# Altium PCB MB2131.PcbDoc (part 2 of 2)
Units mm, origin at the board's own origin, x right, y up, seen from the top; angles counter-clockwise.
Board outline 22 x 56 mm, 2 copper layers (Top Layer, Bottom Layer), stack 0.87 mm thick; 89 components, 71 nets, 391 pads, 308 vias.
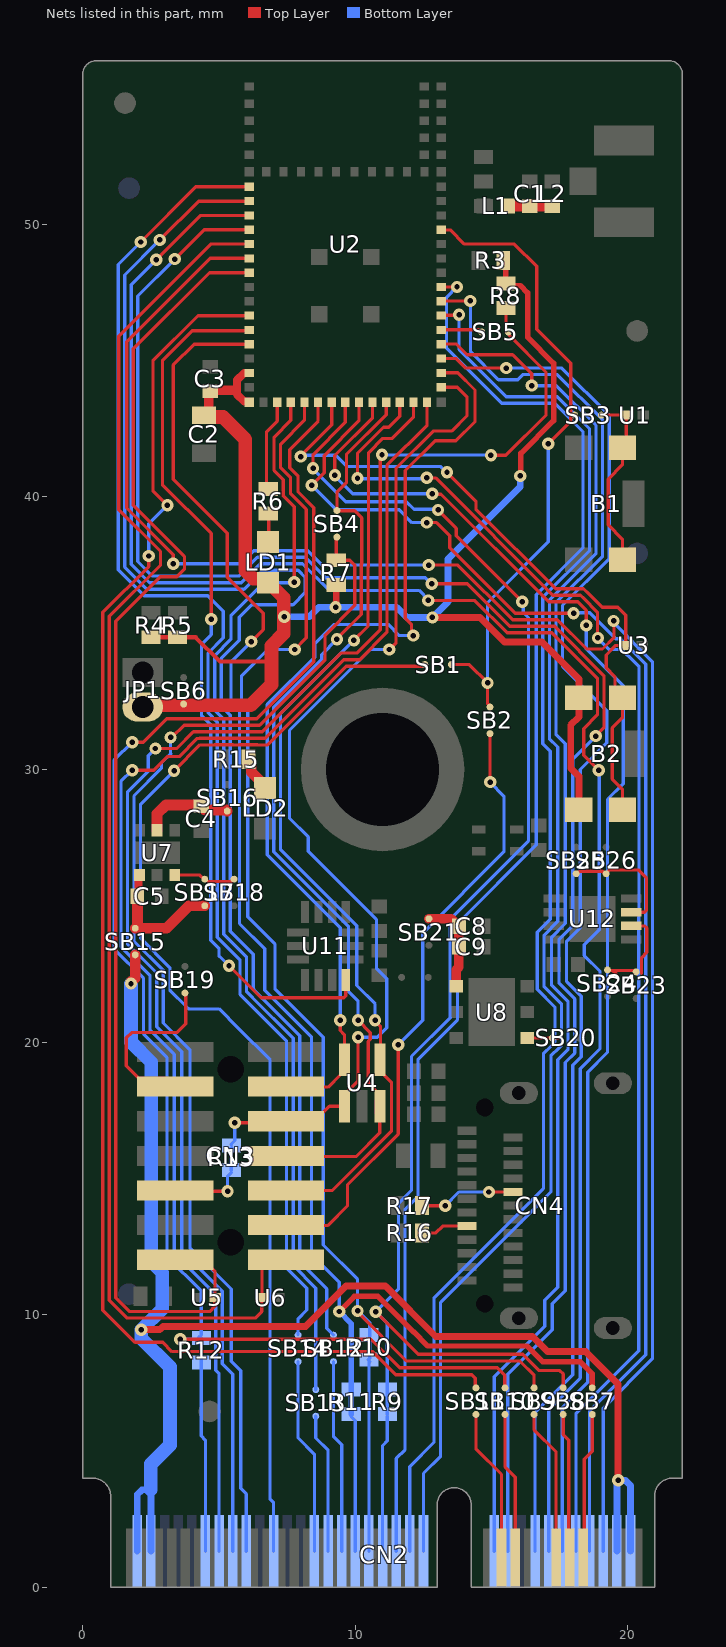
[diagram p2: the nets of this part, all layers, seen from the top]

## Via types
v1: diameter 0.45, hole 0.2, Top Layer to Bottom Layer, tented both sides, 308 vias

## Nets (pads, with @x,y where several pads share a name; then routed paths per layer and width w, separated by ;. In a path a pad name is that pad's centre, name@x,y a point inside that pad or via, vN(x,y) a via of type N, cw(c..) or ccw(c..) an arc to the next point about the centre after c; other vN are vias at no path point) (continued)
JTDI: CN3.10 U2.34 U4.4 | length 35.1
  Top Layer w0.12: CN3.10@7.457,14.555 9.155,14.555 11.325,16.725 11.325,18.525 U4.4@11.025,18.825 ; v1(9.949,34.734) 10.461,35.246 10.461,37.437 10.485,37.461 10.485,41.626 11.005,42.146 11.353,42.146 12.133,42.926 U2.34@12.133,43.475 ; v1(10.725,20.8) 10.725,20.765 10.925,20.565 U4.4@10.925,19.075
  Bottom Layer w0.12: v1(9.949,34.734) 9.943,34.734 7.252,32.043 7.252,27.073 10.05,24.275 10.05,22.075 10.725,21.4 v1(10.725,20.8)
M2_3V3: CN2.2 CN2.4 CN2.72 CN2.74 SB15.1 | length 54.8
  Top Layer w0.25: v1@2.157,9.453 2.828,9.453 2.945,9.57 8.179,9.57 9.659,11.05 11.1,11.05 12.95,9.2 16.5,9.2 17.05,8.65 18.45,8.65 19.641,7.459 v1(19.641,3.922)
  Top Layer w0.4: v1(1.77,22.145) 1.77,22.199 1.925,22.354 SB15.1@1.925,23.2
  Bottom Layer w0.25: 2,3.4 2.174,3.575 2.5,3.575 CN2.72@2.5,1.325 ; CN2.74@2,1.325 2,3.4 ; CN2.4@19.594,1.325 19.594,3.821 19.641,3.868 v1(19.641,3.922) 19.906,3.922 20.094,3.734 CN2.2@20.094,1.325
  Bottom Layer w0.5: v1(1.77,22.145) 1.77,20 2.512,19.258 2.512,11.942 2.914,11.54 2.914,10.21 v1(2.148,9.443) 2.148,9.13 3.2,8.078 3.2,5.22 2.5,4.52 2.5,3.575
NetB1_1: B1.1 B1.3 SB3.2 U1.1 | length 6.6
  Top Layer w0.12: SB3.2@19.025,43 U1.1@19.938,43 19.938,41.813 B1.3@19.925,41.8 ; B1.1@19.8,37.75 19.8,38.45 19.275,38.975 19.275,40.65 19.8,41.175 B1.3@19.8,41.8
NetB2_1: B2.1 B2.3 U2.28 U3.1 | length 25
  Top Layer w0.12: v1(7.994,41.478) 7.994,41.507 9.133,42.645 U2.28@9.133,43.475 ; v1(13.362,40.905) 14.425,39.842 14.425,39.55 17.345,36.63 18.37,36.63 18.575,36.425 19.05,35.95 19.625,35.95 19.921,35.654 19.921,34.571 U3.1@19.9,34.55 19.55,34.55 19.2,34.2 19.2,33.725 19.525,33.4 B2.3@19.525,32.725 ; B2.1@19.775,28.525 19.8,28.55 19.8,29.275 19.425,29.65 19.425,31.525 19.8,31.9 B2.3@19.8,32.625
  Bottom Layer w0.12: v1(7.994,41.478) 8.042,41.525 9.275,41.525 9.684,41.116 13.116,41.116 13.32,40.912 v1@13.355,40.912
NetC1_2: C1.2 L1.2 L2.1 | length 1.6
  Top Layer w0.4: L1.2@15.6,50.675 C1.2@16.4,50.675 L2.1@17.225,50.675
NetC4_2: C4.2 SB16.1 U7.5 | length 3.4
  Top Layer w0.4: U7.5@2.725,27.775 2.725,28.375 3.05,28.7 4.3,28.7 4.488,28.512 5.263,28.512 SB16.1@5.3,28.475
NetC5_2: C5.2 SB15.2 SB17.1 U7.1 | length 5
  Top Layer w0.3: C5.2@2,25.35 2.042,25.392 2.042,26.092 U7.1@2.075,26.125 2.075,26.15 U7.1@2.025,26.2
  Top Layer w0.4: C5.2@2.004,25.346 2.004,24.254 SB15.2@1.925,24.175 3.071,24.175 3.896,25 SB17.1@4.475,25
NetC8_2: C8.2 C9.2 SB21.1 U8.4 | length 3.4
  Top Layer w0.35: SB21.1@12.7,24.525 13.525,24.525 13.695,24.355 13.72,24.355 13.8,24.275 C8.2@13.8,24.25 C9.2@13.8,23.5 ; U8.4@13.7,22.05 13.7,22.65 13.8,22.75 C9.2@13.8,23.475
NetCN2_6: CN2.6 U2.12 | length 68.7
  Top Layer w0.12: v1(3.325,37.55) 3.325,37.882 1.615,39.592 1.615,45.69 4.675,48.75 U2.12@6.108,48.75 ; v1(12.691,37.499) 13.762,37.499 15.769,35.492 17.412,35.492 18.484,34.42 19.068,34.42 19.492,34.844 19.492,35.432 v1(19.474,35.449)
  Bottom Layer w0.12: v1(3.325,37.55) 5.8,37.55 6.275,38.025 8.26,38.025 8.786,37.499 v1(12.691,37.499) ; CN2.6@19.094,1.325 19.094,6.569 20.9,8.375 20.9,33.958 19.474,35.384 v1(19.474,35.449)
NetCN2_8: CN2.8 U2.30 | length 52.4
  Top Layer w0.12: v1(8.4,40.425) 8.855,40.88 8.855,41.513 10.133,42.79 U2.30@10.133,43.475 ; v1(12.616,39.058) 12.981,39.058 13.465,38.574 13.465,38.135 15.868,35.732 v1(18.005,35.732)
  Bottom Layer w0.12: v1(8.4,40.425) 9.3,39.525 11.611,39.525 12.078,39.058 v1(12.616,39.058) ; v1(18.005,35.732) 18.022,35.749 18.602,35.749 19.551,34.8 19.718,34.8 20.65,33.868 20.65,8.525 18.594,6.469 CN2.8@18.594,1.325
NetCN2_9: CN2.9 SB7.1 | length 5.4
  Top Layer w0.12: CN2.9@18.363,1.075 18.4,1.112 18.4,4.7 18.69,4.99 SB7.1@18.69,6.339
NetCN2_10: CN2.10 U2.33 | length 50.7
  Top Layer w0.12: v1(10.08,40.679) 10.08,41.599 11.033,42.552 11.222,42.552 11.633,42.962 U2.33@11.633,43.475 ; v1(12.616,40.701) 12.623,40.694 12.942,40.694 17.246,36.39 18.26,36.39 18.375,36.275 ; 18.375,36.275 18.882,35.767 18.882,34.843 v1(18.9,34.825)
  Bottom Layer w0.12: v1(10.08,40.679) 10.093,40.666 12.582,40.666 v1(12.616,40.701) ; CN2.10@18.094,1.325 18.094,6.369 20.4,8.675 20.4,24.575 20.41,24.585 20.41,33.765 20.225,33.95 ; v1(18.9,34.825) 18.9,34.812 19.319,34.394 19.325,34.4 19.779,34.4 20.227,33.952
NetCN2_11: CN2.11 SB8.1 | length 5.4
  Top Layer w0.12: SB8.1@17.624,6.339 17.624,5.601 17.825,5.4 17.825,1.112 CN2.11@17.863,1.075
NetCN2_12: CN2.12 U2.31 | length 50.6
  Top Layer w0.12: v1(9.252,40.799) 9.246,40.804 9.246,41.518 10.633,42.904 U2.31@10.633,43.475 ; v1(12.823,40.111) 12.835,40.098 13.143,40.098 17.091,36.15 18.16,36.15 18.476,35.834 v1(18.476,35.284)
  Bottom Layer w0.12: v1(9.252,40.799) 9.252,40.766 9.907,40.111 v1(12.823,40.111) ; CN2.12@17.594,1.325 17.594,6.594 18.525,7.525 18.525,18.9 19.25,19.625 19.25,28.9 19.825,29.475 19.825,33.075 18.468,34.432 18.468,35.276 v1(18.476,35.284)
NetCN2_13: CN2.13 SB9.1 | length 5.6
  Top Layer w0.12: SB9.1@16.558,6.339 16.558,5.767 17.363,4.962 CN2.13@17.363,1.075
NetCN2_14: CN2.14 U2.9 | length 68.9
  Top Layer w0.12: v1(2.7,48.7) 4.325,50.325 5.55,50.325 U2.9@6.108,50.325 ; v1(12.675,36.201) 12.679,36.198 14.384,36.198 15.57,35.012 17.213,35.012 18.88,33.345 18.88,32.005 18.375,31.5 18.375,30.525 v1(18.925,29.975)
  Bottom Layer w0.12: 1.78,37.524 2.449,36.855 5.819,36.855 6.509,37.545 8.061,37.545 9.038,36.569 12.336,36.569 12.675,36.23 v1(12.675,36.201) ; 1.85,37.46 1.78,37.531 1.78,47.78 v1(2.7,48.7) ; CN2.14@17.094,1.325 17.094,6.519 18.25,7.675 18.25,19.025 18.975,19.75 18.975,22.6 18.4,23.175 18.4,23.575 18.95,24.125 18.95,29.95 v1(18.925,29.975)
NetCN2_16: CN2.16 U2.39 | length 51.6
  Top Layer w0.12: U2.39@13.158,45.075 13.709,45.075 14.057,44.727 v1(15.536,44.727)
  Bottom Layer w0.12: v1(15.536,44.727) 17.573,44.727 19.31,42.99 19.31,37.727 17.6,36.017 17.6,33.775 19.225,32.15 19.225,30.975 18.25,30 18.25,24.2 17.75,23.7 17.75,22.218 18.285,21.683 18.285,19.46 18.175,19.35 17.975,19.15 17.975,7.8 16.594,6.419 CN2.16@16.594,1.325
NetCN2_19: CN2.19 SB10.1 | length 5.4
  Top Layer w0.12: SB10.1@15.491,6.339 15.491,4.409 15.863,4.037 CN2.19@15.863,1.075
NetCN2_20: CN2.20 U2.10 | length 68.3
  Top Layer w0.12: v1(3.375,48.725) 4.452,49.802 U2.10@6.108,49.802 ; v1(12.804,36.813) 14.108,36.813 15.669,35.252 17.313,35.252 19.12,33.444 19.12,31.525 v1(18.82,31.225)
  Bottom Layer w0.12: v1(3.375,48.725) 2.02,47.37 2.02,37.63 2.555,37.095 5.72,37.095 6.41,37.785 8.161,37.785 8.916,37.03 12.569,37.03 12.786,36.813 v1(12.804,36.813) ; CN2.20@15.594,1.325 15.594,7.819 17.225,9.45 17.225,10.4 17.7,10.875 17.7,19.25 18.045,19.595 18.045,21.584 17.475,22.154 17.475,23.775 17.975,24.275 17.975,30.38 v1(18.82,31.225)
NetCN2_21: CN2.21 SB11.1 | length 5.7
  Top Layer w0.12: SB11.1@14.425,6.339 14.425,5.075 15.363,4.137 CN2.21@15.363,1.075
NetCN2_22: CN2.22 U2.43 | length 52.9
  Top Layer w0.12: U2.43@13.158,47.175 13.165,47.183 14.208,47.183 v1(14.216,47.19)
  Bottom Layer w0.12: v1(14.216,47.19) 14.229,47.177 14.229,45.321 15.25,44.3 15.954,44.3 16.141,44.487 17.413,44.487 19.07,42.83 19.07,37.827 17.36,36.117 17.36,31.29 17.7,30.95 17.7,24.35 17.2,23.85 17.2,22.089 17.805,21.484 17.805,19.73 17.425,19.35 17.425,11 16.95,10.525 16.95,9.575 15.094,7.719 CN2.22@15.094,1.325
NetCN2_32: CN2.32 U2.40 | length 51.9
  Top Layer w0.12: U2.40@13.158,45.6 13.167,45.609 13.704,45.609 14.096,45.218 15.768,45.218 16.472,44.513 v1(16.472,44.082)
  Bottom Layer w0.12: CN2.32@12.5,1.325 12.5,4.175 13.125,4.8 13.125,10.45 16.375,13.7 17.175,14.5 17.175,19.5 17.475,19.8 17.565,19.89 17.565,21.385 16.925,22.025 16.925,23.925 17.425,24.425 17.425,30.825 17.12,31.13 17.12,36.216 18.83,37.926 18.83,42.62 17.368,44.082 v1(16.472,44.082)
NetCN2_34: CN2.34 U2.42 | length 52.6
  Top Layer w0.12: U2.42@13.158,46.65 13.173,46.666 13.791,46.666 v1(13.807,46.682)
  Bottom Layer w0.12: CN2.34@12,1.325 12,4.425 12.885,5.31 12.885,10.61 16.9,14.625 16.9,19.575 17.2,19.875 17.325,20 17.325,21.286 16.675,21.936 16.675,24.025 17.15,24.5 17.15,30.675 16.88,30.945 16.88,36.316 18.59,38.026 18.59,42.498 17.411,43.677 16.305,43.677 15.533,43.677 13.807,45.404 v1(13.807,46.682)
NetCN2_36: CN2.36 U2.44 | length 53.2
  Top Layer w0.12: U2.44@13.158,47.7 13.158,47.701 v1(13.729,47.702) v1(13.729,47.702)
  Bottom Layer w0.12: CN2.36@11.5,1.325 11.5,4.725 11.825,5.05 11.825,13.875 12.3,14.35 12.3,19.375 13.75,20.825 13.75,24.35 16.64,27.24 16.64,36.415 18.35,38.125 18.35,42.398 17.317,43.431 15.37,43.431 13.347,45.454 13.347,47.32 v1(13.729,47.702)
NetCN2_44: CN2.44 SB12.2 | length 7.1
  Bottom Layer w0.12: SB12.2@9.2,8.275 9.2,5.525 9.5,5.225 CN2.44@9.5,1.325
NetCN2_46: CN2.46 SB13.2 | length 5.1
  Bottom Layer w0.12: SB13.2@8.55,6.275 8.55,5.475 9,5.025 CN2.46@9,1.325
NetCN2_48: CN2.48 SB14.2 | length 7.2
  Bottom Layer w0.12: SB14.2@7.9,8.275 7.9,5.475 8.5,4.875 CN2.48@8.5,1.325
NetCN2_54: CN2.54 SB1.2 | length 42.6
  Top Layer w0.12: v1(3.35,29.95) 4.3,30.9 4.84,30.9 4.845,30.905 5.505,30.905 5.51,30.9 5.74,30.9 5.745,30.905 6.405,30.905 6.41,30.9 6.782,30.9 9.672,33.79 12.48,33.79 12.532,33.842 SB1.2@12.558,33.842
  Bottom Layer w0.12: v1(3.35,29.95) 2.12,28.72 2.12,23.805 3.2,22.725 3.2,21.9 3.825,21.275 3.885,21.215 4.41,21.215 4.999,21.215 5.699,20.515 6.871,19.343 6.871,19.054 6.871,3.229 7,3.1 CN2.54@7,1.325
NetCN2_58: CN2.58 R7.2 SB4.2 | length 44.5
  Top Layer w0.12: v1(3.222,31.174) 3.268,31.174 3.719,31.625 6.488,31.625 8.89,34.027 8.89,34.926 9.981,36.017 9.981,37.494 9.8,37.675 R7.2@9.3,37.675 SB4.2@9.3,38.5
  Bottom Layer w0.12: 3.222,30.575 v1(3.222,31.174) ; 3.225,30.575 2.887,30.237 2.887,30.037 1.88,29.03 1.88,23.703 2.95,22.633 2.95,20.7 3.933,19.717 3.933,12.458 5.45,10.941 5.45,8.284 5.796,7.939 5.796,3.627 6,3.422 CN2.58@6,1.325
NetCN2_60: CN2.60 R8.2 SB5.2 | length 59
  Top Layer w0.12: v1(2.667,30.769) 3.444,30.769 4.06,31.385 6.588,31.385 9.473,34.27 10.058,34.27 10.918,35.13 10.918,41.486 v1(10.979,41.547) ; v1(14.975,41.525) 15.525,41.525 16.995,42.995 16.995,44.572 15.638,45.929 15.638,46.024 SB5.2@15.613,46.05 ; R8.2@15.525,46.75 15.525,46.082 SB5.2@15.585,46.023
  Bottom Layer w0.12: v1(2.667,30.769) 2.405,30.507 2.405,29.93 1.64,29.165 1.64,23.604 2.71,22.534 2.71,20.565 3.635,19.64 3.635,12.352 5.12,10.866 5.12,8.197 5.5,7.817 CN2.60@5.5,1.325 ; v1(10.979,41.547) 10.99,41.536 14.964,41.536 v1(14.975,41.525)
NetCN2_62: CN2.62 U2.35 | length 50.8
  Top Layer w0.12: v1(1.815,29.975) 2.6,29.975 3.1,30.475 3.536,30.475 4.201,31.14 4.276,31.14 4.281,31.145 6.687,31.145 9.572,34.03 10.158,34.03 11.158,35.03 11.158,41.154 12.633,42.628 U2.35@12.633,43.475
  Bottom Layer w0.12: v1(1.815,29.975) 1.4,29.56 1.4,23.504 2.47,22.434 2.47,20.43 3.354,19.546 3.354,12.256 4.88,10.73 4.88,7.96 5,7.84 5,6.125 CN2.62@5,1.325
NetCN4_A5: CN4.A5 R16.1 | length 1.7
  Top Layer w0.12: R16.1@12.45,13 12.95,13 13.2,13.25 CN4.A5@14.09,13.25
NetCN4_B5: CN4.B5 R17.1 | length 3.6
  Top Layer w0.12: R17.1@12.374,14 v1(13.3,14) ; v1(14.9,14.5) CN4.B5@15.79,14.5
  Bottom Layer w0.12: v1(13.3,14) 13.8,14.5 v1(14.9,14.5)
NetLD1_2: LD1.2 R6.2 | length 1
  Top Layer w0.12: LD1.2@6.825,38.35 R6.2@6.825,39.391
NetLD2_1: LD2.1 R15.1 | length 1.2
  Top Layer w0.4: R15.1@6.075,30.375 6.18,30.27 6.18,29.909 LD2.1@6.69,29.4
NetR6_1: R6.1 U2.24 | length 3.4
  Top Layer w0.12: R6.1@6.804,40.294 6.744,40.354 6.744,42.394 7.133,42.783 U2.24@7.133,43.475
NetSB1_1: SB1.1 SB2.1 SB3.1 U2.48 | length 23.6
  Top Layer w0.12: U2.48@13.165,49.795 13.482,49.795 14.002,49.275 15.832,49.275 16.65,48.457 16.65,46.15 17.9,44.9 17.9,42.925 17.9,42.775 v1@17.1,41.975 ; SB1.1@13.525,33.85 14.175,33.85 v1(14.85,33.175) 14.85,32.416 14.94,32.326 SB2.1@14.94,32.29
  Bottom Layer w0.12: v1(14.85,33.175) 14.85,36.125 17.075,38.35 v1(17.075,41.95)
NetSB5_1: SB5.1 U2.41 | length 1.5
  Top Layer w0.12: U2.41@13.165,46.133 13.717,46.133 13.719,46.131 14.521,46.131 14.601,46.05 SB5.1@14.638,46.05
NetSB11_2: SB11.2 U2.16 | length 55.3
  Top Layer w0.12: v1@2.417,37.823 2.417,37.446 0.735,35.764 0.735,10.165 1.914,8.986 2.932,8.986 3.271,8.646 3.275,8.65 10.625,8.65 11.475,7.8 14.271,7.8 14.396,7.675 14.396,7.384 14.399,7.381 14.399,7.346 SB11.2@14.428,7.317 ; v1(3.107,39.696) 2.575,40.227 2.575,44.989 4.228,46.643 6.1,46.643 U2.16@6.108,46.65
  Bottom Layer w0.12: v1(2.425,37.832) 2.425,39.014 v1(3.107,39.696)
NetSB12_1: SB12.1 U2.8 | length 55.4
  Top Layer w0.12: v1(2.825,49.425) 4.25,50.85 U2.8@6.108,50.85
  Bottom Layer w0.12: v1(2.825,49.425) 1.54,48.14 1.54,37.424 2.349,36.615 5.919,36.615 6.609,37.305 7.9,37.305 8.162,37.043 8.162,36.495 7.715,36.048 6.198,36.048 5.74,35.59 5.74,34.736 5.079,34.075 5.079,32.33 5.415,31.994 5.415,24.06 6.25,23.225 6.25,21.95 6.35,21.85 ; 6.347,21.847 7.958,20.235 7.958,11.936 8.949,10.944 8.949,9.501 SB12.1@9.2,9.25
NetSB13_1: SB13.1 U2.25 | length 40.2
  Top Layer w0.12: U2.25@7.633,43.475 7.633,42.808 7.018,42.193 7.018,40.965 7.359,40.624 7.359,40.041 7.757,39.643 v1(7.757,36.875)
  Bottom Layer w0.12: v1@7.807,36.85 6.64,36.85 5.436,35.645 5.436,34.771 4.839,34.174 4.839,32.174 5.175,31.837 5.175,23.95 6.01,23.115 6.01,21.844 6.214,21.639 6.227,21.627 7.718,20.136 7.718,11.807 8.55,10.975 SB13.1@8.55,7.25
NetSB14_1: SB14.1 U2.7 | length 50.1
  Top Layer w0.12: v1(2.125,49.35) 4.15,51.375 U2.7@6.108,51.375
  Bottom Layer w0.12: v1(2.125,49.35) 1.3,48.525 1.3,37.325 2.25,36.375 4.586,36.375 5.153,35.808 5.153,34.828 4.599,34.274 4.599,32.074 4.935,31.738 4.935,23.84 5.77,23.005 5.77,21.744 5.932,21.582 5.945,21.57 7.478,20.036 7.478,11.707 8.221,10.964 8.221,10.171 7.9,9.85 SB14.1@7.9,9.25
NetSB17_2: SB17.2 SB18.2 U7.3 | length 2.3
  Top Layer w0.12: U7.3@3.375,26.125 4.3,26.125 4.45,25.975 4.511,25.975 4.596,25.89 5.429,25.89 5.514,25.975 SB18.2@5.55,25.975
NetSB20_2: SB20.2 U8.1 | length 1.2
  Top Layer w0.12: U8.1@16.3,20.15 17.475,20.15
NetSB23_1: SB23.1 SB24.2 U12.2 | length 3.4
  Top Layer w0.12: SB24.2@19.361,22.625 SB23.1@20.3,22.625 ; 19.45,22.6 19.486,22.6 19.561,22.525 ; U12.2@20.132,24.258 20.619,24.258 20.69,24.187 20.69,23.29 20.5,23.1 20.5,22.525
NetSB25_2: SB25.2 SB26.2 U12.3 | length 4.6
  Top Layer w0.12: SB25.2@18.1,26.175 18.136,26.175 18.23,26.268 19.07,26.268 19.164,26.175 SB26.2@19.2,26.175 19.2,26.178 19.337,26.315 20.385,26.315 20.68,26.02 20.68,24.835 20.61,24.765 U12.3@20.125,24.765
NetU2_17: U2.17 U11.4 | length 32.5
  Top Layer w0.12: v1(4.714,35.512) 4.714,38.661 2.925,40.45 2.925,45 4.017,46.092 6.074,46.092 U2.17@6.108,46.125 ; v1(5.365,22.8) 6.54,21.625 9.576,21.625 9.646,21.695 U11.4@9.646,22.271
  Bottom Layer w0.12: v1(4.714,35.512) 4.714,34.95 4.359,34.594 4.359,31.975 4.695,31.638 4.695,23.73 5,23.425 5,23.15 ; 5.008,23.158 v1(5.365,22.8)
NRST: CN3.12 SB2.2 | length 22.6
  Top Layer w0.12: CN3.12@7.3,13.275 9,13.275 9.713,13.988 9.713,14.763 11.575,16.625 v1(11.575,19.9) ; SB2.2@14.94,31.315 14.943,31.312 14.943,29.541 v1(14.946,29.538)
  Bottom Layer w0.12: v1(11.575,19.9) 12.475,20.8 12.475,24 15.45,26.975 15.45,29.025 v1@14.95,29.525 ; v1@14.946,29.525 v1(14.946,29.538)
SPI3_MISO: CN2.40 R10.1 R10.2 SB9.2 U2.26 | length 54.3
  Top Layer w0.12: v1(7.774,34.401) 8.2,34.827 8.2,39.539 7.625,40.114 7.625,40.697 7.258,41.064 7.258,41.933 8.133,42.807 U2.26@8.133,43.475 ; v1@10.075,10.1 11.875,8.3 16.033,8.3 16.558,7.775 SB9.2@16.558,7.314
  Bottom Layer w0.12: v1(7.774,34.401) 6.793,34.401 5.82,33.428 5.82,32.583 6.052,32.351 6.052,24.6 6.4,24.252 6.4,24.25 7.05,23.6 7.05,21.95 8.82,20.18 8.82,12.555 10.082,11.293 v1(10.082,10.136) 10.093,10.136 10.525,9.704 10.525,8.4 R10.1@10.475,8.35 ; CN2.40@10.5,1.325 10.5,8.235 10.525,8.26 R10.1@10.525,8.275
SPI3_MOSI: CN2.38 R9.1 R9.2 SB8.2 U2.29 | length 58.5
  Top Layer w0.12: v1(8.45,41.05) 8.45,41.553 9.633,42.735 U2.29@9.633,43.475 ; v1@10.75,10.1 12.3,8.55 16.15,8.55 16.75,7.95 17.5,7.95 17.624,7.826 SB8.2@17.624,7.314 ; v1(13.034,39.523) 13.034,39.515 13.705,38.844 13.705,38.57 v1(16.125,36.15)
  Bottom Layer w0.12: v1(8.45,41.05) 8.45,41.021 9.646,39.825 11.875,39.825 12.152,39.548 13.009,39.548 v1(13.034,39.523) ; CN2.38@11,1.325 11,5.2 11.175,5.375 R9.1@11.175,6.275 ; R9.1@11.175,6.35 R9.2@11.175,7.25 11.175,9.689 v1(10.753,10.111) 11.585,10.943 11.585,14.085 12.06,14.56 12.06,19.474 13.48,20.895 ; 13.475,20.9 13.475,24.5 16.35,27.375 16.35,35.575 16.155,35.77 16.155,36.12 v1(16.125,36.15)
SPI3_NSS: CN2.64 R12.1 R12.2 SB10.2 U2.27 | length 63.1
  Top Layer w0.12: v1(1.815,31.002) 2.222,31.002 3.085,31.865 6.389,31.865 8.475,33.951 8.475,39.604 7.9,40.179 7.9,40.762 7.589,41.072 7.589,41.737 8.633,42.78 U2.27@8.633,43.475 ; v1(3.575,9.1) 10.575,9.1 11.625,8.05 15.211,8.05 15.486,7.775 SB10.2@15.486,7.325
  Bottom Layer w0.12: v1(1.815,31.002) 1.813,31.002 1.16,30.349 1.16,23.405 2.23,22.335 2.23,20.295 3.09,19.435 3.09,12.131 4.35,10.871 R12.2@4.35,9.25 ; v1(3.575,9.1) 4.2,9.1 R12.2@4.3,9.2 ; R12.2@4.325,9.175 R12.2@4.35,9.15 R12.1@4.35,8.25 4.35,5.55 4.5,5.4 CN2.64@4.5,1.325
SPI3_SCK: CN2.42 R11.1 R11.2 SB7.2 U2.18 | length 61.4
  Top Layer w0.12: U2.18@6.108,45.6 4.085,45.6 3.325,44.84 3.325,40.65 5.304,38.671 5.304,37.058 6.625,35.737 6.625,35.133 v1(6.183,34.691)
  Top Layer w0.2: v1(9.41,10.116) 9.962,10.669 10.829,10.669 12.124,9.374 ; 12.125,9.375 12.65,8.85 16.3,8.85 16.875,8.275 18.25,8.275 18.69,7.835 SB7.2@18.69,7.314
  Bottom Layer w0.12: v1(6.183,34.691) 5.443,33.951 5.443,32.564 5.751,32.256 5.751,24.349 6.675,23.425 6.675,21.9 8.395,20.18 8.395,12.206 9.41,11.19 v1(9.41,10.116) ; R11.1@9.85,6.26 10,6.11 CN2.42@10,1.325
  Bottom Layer w0.2: v1(9.41,10.116) 9.85,9.676 R11.2@9.85,7.25 ; R11.1@9.85,6.35 R11.2@9.85,7.2
STDC_3V3: CN3.3 SB19.1 | length 6.6
  Top Layer w0.12: CN3.3@3.393,18.365 3.083,18.675 2.058,18.675 1.6,19.133 1.6,20.155 1.795,20.35 3.45,20.35 3.775,20.675 SB19.1@3.775,21.775
SWCLK: CN3.6 CN3.9 R13.1 R13.2 U2.37 U4.1 | length 41.3
  Top Layer w0.12: CN3.9@3.393,14.555 3.42,14.528 v1(5.311,14.528) ; v1(5.578,17.044) 7.406,17.044 CN3.6@7.457,17.095 7.767,17.405 8.805,17.405 9.05,17.65 U4.1@9.6,17.65 ; U4.1@9.74,17.65 U4.1@9.74,17.821 ; U4.1@9.74,18.221 10.1,18.581 10.1,20.174 v1(10.099,20.175) ; v1(11.246,34.402) 11.249,34.402 11.495,34.648 11.495,41.059 12.851,42.415 13.53,42.415 14.1,42.985 14.1,43.659 13.737,44.022 U2.37@13.16,44.022
  Bottom Layer w0.12: v1(5.311,14.528) 5.311,15.075 R13.1@5.45,15.214 ; R13.1@5.45,15.3 5.45,16.1 R13.2@5.475,16.125 ; R13.2@5.45,16.225 5.45,16.261 5.578,16.39 v1(5.578,17.044) ; v1@10.099,20.175 10.8,20.175 11.15,20.525 11.15,22.325 10.775,22.7 10.775,24.5 8.275,27 8.275,27.525 7.584,28.216 7.584,31.434 10.552,34.402 v1(11.246,34.402)
SWDIO: CN3.4 U2.38 U4.5 | length 36.2
  Top Layer w0.12: CN3.4@7.457,18.365 CN3.4@7.7,18.365 ; CN3.4@7.7,18.35 9,18.35 9.46,18.81 9.46,19.21 U4.5@9.6,19.35 9.6,20.275 9.45,20.425 v1(9.45,20.8) ; v1(12.127,34.913) 12.064,34.976 12.064,35.315 11.835,35.544 11.835,40.967 12.924,42.057 13.692,42.057 14.39,42.755 14.39,43.922 13.762,44.55 U2.38@13.158,44.55
  Bottom Layer w0.12: v1(9.45,20.8) 9.45,24.196 6.772,26.874 6.772,27.064 6.772,32.386 8.524,34.138 8.524,34.625 9.222,35.323 11.202,35.323 11.612,34.913 v1(12.127,34.913)
SWO: CN3.8 SB4.1 U2.32 U4.3 | length 34.8
  Top Layer w0.12: CN3.8@7.457,15.825 7.482,15.8 10.025,15.8 10.9,16.675 U4.3@10.9,17.263 ; v1(9.325,34.775) 9.325,34.79 10.221,35.686 10.221,37.537 10.235,37.551 10.235,39.229 9.972,39.493 SB4.1@9.332,39.493 ; SB4.1@9.325,39.5 9.325,40.167 9.675,40.517 9.675,41.555 11.133,43.013 U2.32@11.133,43.475 ; v1(10.1,20.8) 10.55,20.35 10.55,20.1 10.475,20.025 10.475,18.5 10.575,18.4 U4.3@10.775,18.2 ; U4.3@10.76,17.843 10.76,17.39 U4.3@10.887,17.263
  Bottom Layer w0.12: v1(9.325,34.775) 8.764,34.214 8.764,34.039 7.012,32.287 7.012,26.974 9.75,24.236 9.75,21.85 10.1,21.5 v1(10.1,20.8)
VCP_RX: CN3.13 U2.13 U5.1 | length 49.2
  Top Layer w0.12: CN3.13@3.393,12.015 4.418,12.015 4.728,11.705 4.728,11.704 4.854,11.578 U5.1@4.854,10.638 ; U5.1@4.845,10.63 4.845,10.302 4.658,10.115 1.725,10.115 1.215,10.625 1.215,35.446 2.837,37.068 3.456,37.068 3.73,37.342 3.73,37.816 1.855,39.691 1.855,45.43 4.65,48.225 U2.13@6.108,48.225
VCP_TX: CN3.14 U2.11 U6.1 | length 51.6
  Top Layer w0.12: U2.11@6.108,49.275 4.7,49.275 1.325,45.9 1.325,39.525 2.853,37.997 2.853,37.494 0.975,35.617 0.975,10.526 1.626,9.875 6.325,9.875 6.563,10.113 U6.1@6.563,10.625 ; U6.1@6.55,10.625 6.575,10.65 6.575,11.85 7.292,11.85 CN3.14@7.457,12.015 CN3.14@7.472,12
VDD_MCU: B2.2 B2.4 C2.2 C3.2 JP1.2 LD1.1 R3.2 R4.1 R5.1 R7.1 R8.1 SB6.2 U2.20 U2.22 | length 59.1
  Top Layer w0.15: R4.1@2.5,34.85 R5.1@3.475,34.85 4.145,34.85 5.029,33.966 6.835,33.966
  Top Layer w0.2: 6.819,33.95 6.835,33.966 6.925,34.056 ; R3.2@15.425,48.6 15.525,48.5 R8.1@15.525,47.825 ; R8.1@15.525,47.75 15.528,47.747 16.058,47.747 16.317,47.488 16.317,45.861 17.275,44.903 17.275,42.8 16.069,41.594 16.069,40.785 v1(16.053,40.769)
  Top Layer w0.25: v1@9.3,35.974 R7.1@9.3,36.775 ; v1(12.829,35.579) 12.918,35.579 12.922,35.576 14.575,35.576 15.475,34.675 16.85,34.675 18.2,33.325 B2.4@18.2,32.65 ; B2.2@18.2,28.525 18.2,29.75 17.9,30.05 17.9,31.625 18.2,31.925 B2.4@18.2,32.625
  Top Layer w0.3: C3.2@4.675,43.875 C3.2@4.714,43.914 ; 5.551,43.914 5.663,44.025 ; U2.22@6.108,43.475 6.083,43.5 5.926,43.5 5.663,43.763 5.663,44.025 ; U2.20@6.108,44.55 5.926,44.55 5.663,44.287 5.663,44.025
  Top Layer w0.35: C2.2@4.478,43 4.623,43.145 4.623,43.816 C3.2@4.678,43.872 ; C3.2@4.714,43.914 5.551,43.914
  Top Layer w0.5: JP1.2@2.2,32.29 2.26,32.35 6.156,32.35 6.925,33.119 6.925,34.056 6.925,34.542 7.369,34.986 v1@7.369,35.574 ; C2.2@4.45,43 4.478,43 4.548,42.93 5.144,42.93 5.968,42.106 5.968,37.293 6.261,37 6.65,37 LD1.1@6.8,36.85 ; LD1.1@6.825,36.85 7.373,36.302 v1@7.373,35.622
  Bottom Layer w0.25: v1(7.395,35.6) 8.307,35.6 8.657,35.95 11.521,35.95 11.892,35.579 v1(12.829,35.579) 13.4,36.15 13.4,37.725 16.053,40.378 v1(16.053,40.769)
  other v1: 9.276,35.95
pads on no net: B1.5 B2.5 CARTOUCH-1.1 CN2.3 CN2.5 CN2.15 CN2.17 CN2.23 CN2.35 CN2.37 CN2.41 CN2.43 CN2.47 CN2.49 CN2.50 CN2.52 CN2.53 CN2.55 CN2.59 CN2.61 CN2.65 CN2.66 CN2.67 CN2.68 CN2.70 CN2.71 CN2.73 CN3.0 CN3.1 CN3.2 CN4.0 CN4.A2 CN4.A3 CN4.A6 CN4.A7 CN4.A8 CN4.A10 CN4.A11 CN4.B2 CN4.B3 CN4.B6 CN4.B7 CN4.B8 CN4.B10 CN4.B11 Designator4.1 Designator5.1 Designator6.1 Designator7.1 Designator8.1 Designator9.1 U2.2 U2.3 U2.4 U2.5 U2.56 U2.59 U7.4 U7.6 U8.3 U8.5 U11.9 U11.10

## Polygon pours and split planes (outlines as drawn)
GND on Top Layer "Top Layer-GND" (solid, remove dead copper, pour order 3): 0,3.337 22,3.337 22,55.6 0,55.6
GND on Bottom Layer "Top Layer-GND" (solid, remove dead copper, pour order 4): 0,3.337 22,3.337 22,55.599 0,55.599

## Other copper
Top Layer:
  pour cut-out: 11.181,23.124 11.306,23.124 11.306,22.62 11.181,22.62
  pour cut-out: 6.18,42.226 6.18,42.351 6.684,42.351 6.684,42.226
  pour cut-out: 19.343,5.027 19.343,4.902 18.839,4.902 18.839,5.027
  pour cut-out: 13.502,22.025 13.502,21.9 12.998,21.9 12.998,22.025
  pour cut-out: 15.184,47.119 15.059,47.119 15.059,47.623 15.184,47.623
  pour cut-out: 14.758,48.204 14.758,48.329 15.262,48.329 15.262,48.204
  pour cut-out: 9.425,19.95 8.975,19.95 8.975,20.125 9.425,20.125
  pour cut-out: 3.54,28.081 3.54,28.206 4.044,28.206 4.044,28.081
  pour cut-out: 14.674,51.081 14.674,51.206 15.178,51.206 15.178,51.081
  pour cut-out: 12.966,43.995 13.111,43.85 12.755,43.493 12.61,43.639
  pour cut-out: 17.815,27.156 17.815,27.281 18.319,27.281 18.319,27.156
  text "1" at 2.078,6.053 h2 r90
Bottom Layer:
  text "2" at 0.85,7 h2 r270
Multi-Layer:
  pour cut-out: 18.85,52.525 18.85,50.625 21.117,50.625 21.117,52.525
  pour cut-out: 6.513,56 6.513,54.767 4.583,54.767 4.583,52.267 12.083,52.267 12.083,54.125 13.45,54.125 13.45,54.725 12.083,54.725 12.083,56
  pour cut-out: 0.575,5.825 2.374,5.825 2.374,8.025 0.575,8.025

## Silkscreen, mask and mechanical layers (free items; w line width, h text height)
Top Overlay:
  circle w0.12: c13.95,27.775 r0.15
  text "MB2131B" at 2.278,45.65 h2 r90
  text "B1-Reset" at 16.988,37.75 h1.2 r90
  text "J" at 15.814,35.207 h10 r90
  text "B2-User" at 17.312,28.825 h1.2 r90
  text "USB:500 mA max" at 21.762,18.8 h1.2 r90
  text "H" at 6.625,3.455 h11
Bottom Overlay:
  text "E" at 13.916,33.907 h10
  text "F" at 20.653,32.481 h10
  text "G" at 21.319,26.907 h10
  text "C" at 7.963,20.722 h10
  text "I" at 13.185,20.62 h10
  text "S" at 21.208,19.5 h10
Top Solder:
  region: 2.328,5.803 2.328,8 0.625,8 0.625,5.803
Bottom Solder:
  region: 2.328,5.875 2.328,7.975 0.625,7.975 0.625,5.875
  region: 5.575,15.95 5.325,15.95 5.325,15.55 5.575,15.55
  region: 4.475,8.9 4.225,8.9 4.225,8.5 4.475,8.5
  region: 9.975,7 9.725,7 9.725,6.6 9.975,6.6
  region: 11.3,6.975 11.05,6.975 11.05,6.575 11.3,6.575
  region: 10.65,9 10.4,9 10.4,8.6 10.65,8.6
M1-Board Shape:
  lines w0.1: 0,4 0,55.5 cw(c0.5,55.5) 0.5,56 21.5,56 cw(c21.5,55.5) 22,55.5 22,4
Drill Drawing:
  drawing of 304 lines, arcs and shapes, not listed
  text "PCB SPECIFICATIONS :" at -31.666,103.912 h3
  text "A.   MATERIAL :" at -31.666,99.912 h3
  text "FR-4" at 6.834,99.912 h3
  text "TG-170" at 23.334,99.912 h3
  text "X  TG-150" at 41.584,99.912 h3
  text "TG-140" at 57.584,99.912 h3
  text "B.   MATERIAL FAMILY :" at -31.666,96.912 h3
  text "N/A" at 6.834,96.912 h3
  text "C.   SOLDERMASK COLOR :" at -31.666,93.912 h3
  text "GREEN" at 6.834,93.912 h3
  text "WHITE" at 23.334,93.912 h3
  text "RED" at 41.584,93.912 h3
  text "X  Blue ink PANTONE 2955" at 57.584,93.912 h3
  text "BLACK" at 41.646,90.939 h3
  text "D.   SILKSCREEN COLOR :" at -31.666,90.912 h3
  text "X  WHITE" at 6.834,90.912 h3
  text "YELLOW" at 23.334,90.912 h3
  text "E.   SURFACE FINISH :" at -31.666,87.912 h3
  text "X  ENIG" at 6.834,87.912 h3
  text "IMMERSION SILVER" at 23.334,87.912 h3
  text "IMMERSION TIN" at 57.584,87.912 h3
  text "HASL" at 6.834,84.912 h3
  text "HASL (PB-FREE)" at 23.334,84.912 h3
  text "GOLDEN FINGER" at 57.584,84.912 h3
  text "F.   IMPEDANCE CONTROL :" at -31.666,81.912 h3
  text "NO" at 6.834,81.912 h3
  text "X  YES (SEE IMPEDANCE FILE)" at 23.334,81.912 h3
  text "G.   THROUGH VIA :" at -31.666,78.912 h3
  text "PLUG THE VIAS WHICH ARE COVERED WITH SOLDERMASK ONE OR TWO SIDE." at 6.834,78.912 h3
  text "PLUG MATERIAL :" at 6.834,75.912 h3
  text "X  SOLDERMASK" at 32.334,75.912 h3
  text "NON-CONDUCTIVE EPOXY." at 57.584,75.912 h3
  text "H.   STACK-UP :" at -31.666,72.912 h3
  text "SEE LAYER STACK-UP SEQUENCE FOR OVERALL THICKNESS." at 6.834,72.912 h3
  text "PCB : TYPE 2" at 106.086,63.25 h3
  text "ASPECT-RATIO, AXE Z :" at 106.086,57.75 h3
  text "<6 :1 / LEVEL \"A\"" at 106.105,51.002 h3
  text "Layer" at 35.173,49.884 h1.52
  text "Name" at 41.551,49.884 h1.52
  text "Material" at 53.884,49.884 h1.52
  text "Thickness" at 64.968,49.884 h1.52
  text "Constant" at 74.072,49.884 h1.52
  text "Board Layer Stack" at 82.498,49.884 h1.52
  text "Top Overlay" at 41.551,46.836 h1.52
  text "Top Solder" at 41.551,43.788 h1.52
  text "Solder Resist" at 53.884,43.788 h1.52
  text "0.015mm" at 64.968,43.788 h1.52
  text "3.5" at 74.072,43.788 h1.52
  text "1" at 35.173,40.74 h1.52
  text "Top Layer" at 41.551,40.74 h1.52
  text "0.035mm" at 64.968,40.74 h1.52
  text "MINIMUN PARAMETERS" at 105.867,40.645 h3
  text "Dielectric 1" at 41.551,37.692 h1.52
  text "FR-4" at 53.884,37.692 h1.52
  text "0.800mm" at 64.968,37.692 h1.52
  text "4.8" at 74.072,37.692 h1.52
  text "DEFAULT" at 105.867,35.145 h3
  text "2" at 35.172,34.644 h1.52
  text "Bottom Layer" at 41.551,34.644 h1.52
  text "0.035mm" at 64.968,34.644 h1.52
  text "Bottom Solder" at 41.551,31.596 h1.52
  text "Solder Resist" at 53.884,31.596 h1.52
  text "0.015mm" at 64.968,31.596 h1.52
  text "3.5" at 74.072,31.596 h1.52
  text "TRACKS : 0.120mm           / GAPS : 0.120mm" at 105.867,29.395 h3
  text "Bottom Overlay" at 41.551,28.548 h1.52
  text "Symbol" at 35.302,20.828 h1.83
  text "Count" at 42.462,20.828 h1.83
  text "Hole Size" at 49.888,20.828 h1.83
  text "Plated" at 64.602,20.828 h1.83
  text "Hole Type" at 70.887,20.828 h1.83
  text "Drill Layer Pair" at 80.039,20.828 h1.83
  text "Via/Pad" at 97.382,20.828 h1.83
  text "Pad Shape" at 104.88,20.828 h1.83
  text "Hole Length" at 114.676,20.828 h1.83
  text "Routed Path Length" at 128.591,20.828 h1.83
  text "308" at 42.462,17.674 h1.52
  text "0.200mm (7.87mil)" at 49.888,17.674 h1.52
  text "PTH" at 64.602,17.674 h1.52
  text "Round" at 70.887,17.674 h1.52
  text "Top Layer - Bottom Layer" at 80.039,17.674 h1.52
  text "Via" at 97.382,17.674 h1.52
  text "Rounded" at 104.88,17.674 h1.52
  text "-" at 114.676,17.674 h1.52
  text "-" at 128.591,17.674 h1.52
  text "4" at 42.462,14.52 h1.52
  text "0.500mm (19.69mil)" at 49.888,14.52 h1.52
  text "PTH" at 64.602,14.52 h1.52
  text "Slot" at 70.887,14.52 h1.52
  text "Top Layer - Bottom Layer" at 80.039,14.52 h1.52
  text "Pad" at 97.382,14.52 h1.52
  text "Rounded" at 104.88,14.52 h1.52
  text "1.100mm (43.31mil)" at 114.676,14.52 h1.52
  text "0.600mm (23.62mil)" at 128.591,14.52 h1.52
  text "1" at 42.462,11.366 h1.52
  text "0.650mm (25.59mil)" at 49.888,11.366 h1.52
  text "NPTH" at 64.602,11.366 h1.52
  text "Round" at 70.887,11.366 h1.52
  text "Top Layer - Bottom Layer" at 80.039,11.366 h1.52
  text "Pad" at 97.382,11.366 h1.52
  text "Rounded" at 104.88,11.366 h1.52
  text "-" at 114.676,11.366 h1.52
  text "-" at 128.591,11.366 h1.52
  text "1" at 42.462,8.211 h1.52
  text "0.650mm (25.59mil)" at 49.888,8.211 h1.52
  text "NPTH" at 64.602,8.211 h1.52
  text "Slot" at 70.887,8.211 h1.52
  text "Top Layer - Bottom Layer" at 80.039,8.211 h1.52
  text "Pad" at 97.382,8.211 h1.52
  text "Rounded" at 104.88,8.211 h1.52
  text "0.950mm (37.40mil)" at 114.676,8.211 h1.52
  text "0.300mm (11.81mil)" at 128.591,8.211 h1.52
  text "2" at 42.462,5.057 h1.52
  text "0.800mm (31.50mil)" at 49.888,5.057 h1.52
  text "PTH" at 64.602,5.057 h1.52
  text "Round" at 70.887,5.057 h1.52
  text "Top Layer - Bottom Layer" at 80.039,5.057 h1.52
  text "Pad" at 97.382,5.057 h1.52
  text "(Mixed)" at 104.88,5.057 h1.52
  text "-" at 114.676,5.057 h1.52
  text "-" at 128.591,5.057 h1.52
  text "2" at 42.462,1.903 h1.52
  text "0.970mm (38.19mil)" at 49.888,1.903 h1.52
  text "NPTH" at 64.602,1.903 h1.52
  text "Round" at 70.887,1.903 h1.52
  text "Top Layer - Bottom Layer" at 80.039,1.903 h1.52
  text "Pad" at 97.382,1.903 h1.52
  text "Rounded" at 104.88,1.903 h1.52
  text "-" at 114.676,1.903 h1.52
  text "-" at 128.591,1.903 h1.52
  text "1" at 42.462,-1.251 h1.52
  text "4.150mm (163.39mil)" at 49.888,-1.251 h1.52
  text "PTH" at 64.602,-1.251 h1.52
  text "Round" at 70.887,-1.251 h1.52
  text "Top Layer - Bottom Layer" at 80.039,-1.251 h1.52
  text "Pad" at 97.382,-1.251 h1.52
  text "Rounded" at 104.88,-1.251 h1.52
  text "-" at 114.676,-1.251 h1.52
  text "-" at 128.591,-1.251 h1.52
  text "319 Total" at 42.462,-4.405 h1.52
  text "Slot definitions :" at 35.302,-6.613 h1.52
  text "Routed Path Length" at 45.696,-6.613 h1.52
  text "= Calculated from tool start centre position to tool end centre position." at 58.573,-6.613 h1.52
  text "Hole Length" at 45.696,-7.875 h1.52
  text "= Routed Path Length + Tool Size = Slot length as defined in the PCB layout" at 53.793,-7.875 h1.52

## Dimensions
0,55.4 to 22,55.15 on M2-Board Dimensions
1.025,0 to 0.025,56 on M2-Board Dimensions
